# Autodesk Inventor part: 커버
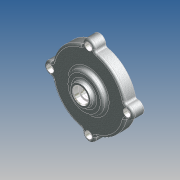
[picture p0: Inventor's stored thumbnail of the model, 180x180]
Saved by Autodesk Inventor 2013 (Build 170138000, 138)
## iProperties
Company: 한국ATC센터
Created: 2014-07
Part Number: 커버
Document SubType Name: 모델링
Designer: KYOUNG IL JANG
Material: 알루미늄 6061
Density: 2.71 g/cm^3
Mass: 196.659 g
Surface Area: 278.607 cm^2
Volume: 72.5678 cm^3
변환 표준: STEP AP214IS
파일 이름: C:\Users\SeoGD\Desktop\?쒗뿕\而ㅻ쾭-1.stp
전처리기: Build: 253, Release: 2010 SP1 - Date: Wed 07/29/2009
전송 단위: 밀리미터
불확실성: 0.01
Author: KYOUNG IL JANG
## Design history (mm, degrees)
sketch "스케치1"
  geometry: L1 (0, 0)-(0, 26); L2 (50, 0)-(50, 15); L3 (50, 15)-(25, 15); L4 (25, 15)-(25, 21); L5 (25, 21)-(15, 21); L6 (15, 21)-(13.66, 26); L7 (13.66, 26)-(10, 26); L8 (50, 0)-(45, 0); L9 (45, 0)-(45, 10); L10 (45, 10)-(14.5, 10); L11 (14.5, 10)-(13.266, 3); L12 (13.266, 3)-(11, 3); L13 (11, 3)-(11, 16); L14 (11, 16)-(7.5, 16); L15 (7.5, 16)-(7.5, 19); L16 (7.5, 19)-(10, 19); L17 (10, 19)-(10, 26)
  constraints: 34 end point, 10 parallel, 2 perpendicular, 2 point on line, 1 vertical
  dimensions: "d11" = 100 diameter of L2 L1; "d12" = 22 diameter of L13 L1; "d13" = 90 diameter of L9 L1; "d14" = 15 distance between parallel lines of L3 L8; "d15" = 10 distance between parallel lines of L8 L10; "d16" = 29 diameter of L10.end L1; "d17" = 100 deg angle of L11 L10; "d18" = 7 distance between parallel lines of L12 L10; "d19" = 13 distance between parallel lines of L14 L12; "d20" = 3 distance between parallel lines of L16 L14; "d21" = 15 diameter of L15 L1; "d22" = 20 diameter of L17 L1; "d23" = 30 diameter of L5.end L1; "d24" = 6 distance between parallel lines of L5 L3; "d25" = 50 diameter of L4 L1; "d26" = 105 deg angle of L5 L6; "d50" = 26 distance of L1.start L1.end
revolve "회전1" sketch "스케치1" stored, may be unused: angle "d27" = 90 deg
sketch "스케치2" dims "d29" = 104
  geometry: A1 r 8.5 centre (0, 52) between (8.074, 49.344) and (-8.074, 49.344); A2 r 50 centre (0, 0) between (-8.074, 49.344) and (8.074, 49.344) reference; 2 further points
  constraints: 4 point on circle, 2 vertical alignment, 1 centre point, 1 coincident, 2 other
  dimensions: "d28" = 17 diameter of A1
extrude "돌출1" join sketch "스케치2" stored distance "d30" = 10; taper "d31" = 0 deg
fillet "모깎기3" dims "d32" = 3
fillet "모깎기4" dims "d45" = 3, "d46" = 0.2
chamfer "모따기1" distance "d47" = 1; stored, may be unused: second distance "d48" = 2, angle "d49" = 45 deg
hole "구멍2" diameter "d38" = 5.5; stored, may be unused: countersink angle "d42" = 90 deg, drill point angle "d44" = 118 deg; dims "d36" = 10, "d37" = 10, "d39" = 6, "d40" = 9.5, "d41" = 5.4, "d43" = 8
node "솔리드1"
node "솔리드 본체"
node "곡면 본체"
pattern_circular "원형 패턴1" dims angle "d34" = 360 deg
pattern_circular "원형 패턴2" dims angle "d52" = 360 deg
node "솔리드2"
